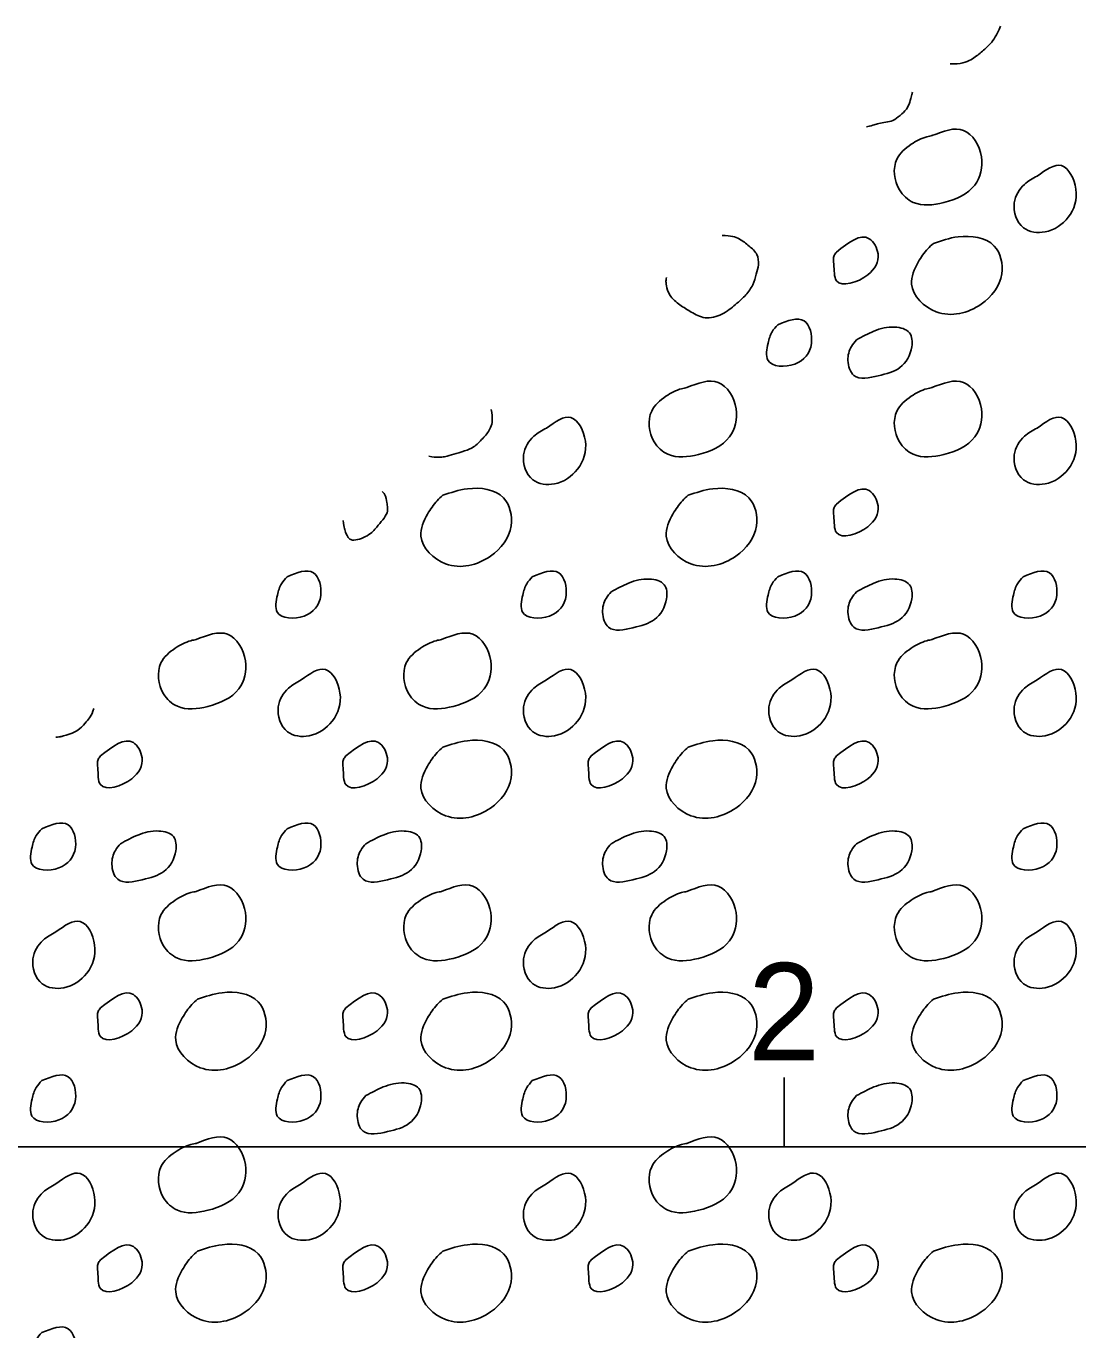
# Model space of a CAD drawing. Extents: x 0 to 1055, y 0 to 220.
# Drawn here: x 206.57 to 221.73, y 144.12 to 162.91 of the extents above; entities that cross this region are included whole.
import ezdxf

# ---------------------------------------------------------------- set-up
doc = ezdxf.new("R2010")
doc.units = 0
for name, color, linetype in [('DR_P_Culvert', 7, 'Continuous'), ('SC_Scratch1', 7, 'Continuous'), ('TX_P_5', 7, 'Continuous')]:
    doc.layers.add(name, color=color, linetype=linetype)

msp = doc.modelspace()

# ---------------------------------------------------------------- linework, layer by layer
at = {"layer": 'DR_P_Culvert'}
msp.add_line((17.5, 146.757), (317.5, 146.757), dxfattribs=at)
at = {"layer": 'SC_Scratch1'}
for points in [[(220.616, 162.908), (220.565, 162.773), (220.472, 162.645), (220.34, 162.532), (220.21, 162.421), (220.045, 162.356), (219.892, 162.363)], [(219.348, 161.954), (219.346, 161.941), (219.343, 161.929), (219.34, 161.917), (219.31, 161.812), (219.271, 161.705), (219.169, 161.62), (219.069, 161.537), (218.963, 161.525), (218.855, 161.5), (218.802, 161.487), (218.745, 161.466), (218.688, 161.457)], [(216.605, 159.89), (216.734, 159.892), (216.863, 159.847), (216.992, 159.739), (217.126, 159.627), (217.135, 159.461), (217.1, 159.337), (217.055, 159.18), (216.956, 159.031), (216.804, 158.902), (216.614, 158.739), (216.35, 158.676), (216.155, 158.791), (215.998, 158.884), (215.832, 159.024), (215.801, 159.189), (215.795, 159.22), (215.796, 159.253), (215.802, 159.285)], [(213.275, 157.384), (213.305, 157.257), (213.281, 157.105), (213.175, 156.988), (213.042, 156.84), (212.894, 156.784), (212.73, 156.735), (212.618, 156.702), (212.495, 156.686), (212.38, 156.71)], [(211.706, 156.203), (211.751, 156.164), (211.776, 156.051), (211.781, 155.995), (211.791, 155.896), (211.714, 155.792), (211.632, 155.693), (211.52, 155.559), (211.24, 155.461), (211.182, 155.609), (211.16, 155.665), (211.151, 155.723), (211.146, 155.782)], [(207.552, 153.077), (207.532, 153.014), (207.499, 152.951), (207.45, 152.893), (207.351, 152.774), (207.237, 152.717), (207.117, 152.681), (207.081, 152.67), (207.041, 152.662), (207.001, 152.662)]]:
    msp.add_open_spline(points, degree=3, dxfattribs=at)
for points in [[(219.63, 161.329), (220.085, 161.405), (220.344, 161.025), (220.247, 160.618), (219.801, 160.366), (219.361, 160.368), (219.162, 160.547), (219.125, 160.992), (219.33, 161.205), (219.556, 161.313), (219.639, 161.331)], [(221.146, 160.747), (221.498, 160.897), (221.705, 160.559), (221.594, 160.154), (221.26, 159.942), (220.95, 160.001), (220.816, 160.36), (220.962, 160.627), (221.146, 160.747)], [(218.252, 159.652), (218.727, 159.844), (218.853, 159.626), (218.704, 159.323), (218.254, 159.239), (218.215, 159.479), (218.219, 159.6), (218.252, 159.652)], [(219.651, 159.777), (220.007, 159.871), (220.528, 159.739), (220.635, 159.337), (220.34, 158.902), (219.691, 158.791), (219.337, 159.189), (219.432, 159.507), (219.57, 159.7), (219.651, 159.777)], [(217.406, 158.604), (217.788, 158.66), (217.892, 158.332), (217.652, 158.038), (217.265, 158.094), (217.268, 158.34), (217.326, 158.504), (217.406, 158.604)], [(218.544, 158.388), (218.794, 158.513), (219.095, 158.57), (219.305, 158.489), (219.34, 158.286), (219.169, 157.989), (218.855, 157.869), (218.504, 157.875), (218.418, 158.091), (218.47, 158.291), (218.544, 158.388)], [(216.095, 157.699), (216.549, 157.774), (216.808, 157.394), (216.711, 156.988), (216.265, 156.735), (215.825, 156.738), (215.626, 156.916), (215.59, 157.361), (215.795, 157.574), (216.02, 157.683), (216.103, 157.7)], [(219.63, 157.699), (220.085, 157.774), (220.344, 157.394), (220.247, 156.988), (219.801, 156.735), (219.361, 156.738), (219.162, 156.916), (219.125, 157.361), (219.33, 157.574), (219.556, 157.683), (219.639, 157.7)], [(214.075, 157.116), (214.426, 157.267), (214.634, 156.929), (214.522, 156.524), (214.189, 156.311), (213.878, 156.37), (213.745, 156.729), (213.89, 156.997), (214.075, 157.116)], [(221.146, 157.116), (221.498, 157.267), (221.705, 156.929), (221.594, 156.524), (221.26, 156.311), (220.95, 156.37), (220.816, 156.729), (220.962, 156.997), (221.146, 157.116)], [(212.58, 156.147), (212.935, 156.24), (213.456, 156.109), (213.564, 155.706), (213.268, 155.271), (212.62, 155.16), (212.265, 155.559), (212.36, 155.877), (212.499, 156.069), (212.58, 156.147)], [(216.115, 156.147), (216.471, 156.24), (216.992, 156.109), (217.1, 155.706), (216.804, 155.271), (216.155, 155.16), (215.801, 155.559), (215.896, 155.877), (216.035, 156.069), (216.115, 156.147)], [(218.252, 156.021), (218.727, 156.214), (218.853, 155.995), (218.704, 155.693), (218.254, 155.609), (218.215, 155.849), (218.219, 155.969), (218.252, 156.021)], [(210.335, 154.974), (210.716, 155.03), (210.82, 154.701), (210.58, 154.407), (210.194, 154.464), (210.196, 154.71), (210.255, 154.873), (210.335, 154.974)], [(213.87, 154.974), (214.252, 155.03), (214.356, 154.701), (214.116, 154.407), (213.73, 154.464), (213.732, 154.71), (213.79, 154.873), (213.87, 154.974)], [(217.406, 154.974), (217.788, 155.03), (217.892, 154.701), (217.652, 154.407), (217.265, 154.464), (217.268, 154.71), (217.326, 154.873), (217.406, 154.974)], [(220.942, 154.974), (221.324, 155.03), (221.428, 154.701), (221.188, 154.407), (220.801, 154.464), (220.804, 154.71), (220.862, 154.873), (220.942, 154.974)], [(215.008, 154.757), (215.258, 154.882), (215.559, 154.94), (215.77, 154.859), (215.804, 154.656), (215.633, 154.359), (215.32, 154.239), (214.968, 154.245), (214.882, 154.461), (214.934, 154.661), (215.008, 154.757)], [(218.544, 154.757), (218.794, 154.882), (219.095, 154.94), (219.305, 154.859), (219.34, 154.656), (219.169, 154.359), (218.855, 154.239), (218.504, 154.245), (218.418, 154.461), (218.47, 154.661), (218.544, 154.757)], [(209.023, 154.068), (209.477, 154.144), (209.736, 153.764), (209.64, 153.357), (209.194, 153.105), (208.754, 153.107), (208.555, 153.286), (208.518, 153.731), (208.723, 153.944), (208.949, 154.052), (209.031, 154.07)], [(212.559, 154.068), (213.013, 154.144), (213.272, 153.764), (213.175, 153.357), (212.73, 153.105), (212.29, 153.107), (212.09, 153.286), (212.054, 153.731), (212.259, 153.944), (212.485, 154.052), (212.567, 154.07)], [(219.63, 154.068), (220.085, 154.144), (220.344, 153.764), (220.247, 153.357), (219.801, 153.105), (219.361, 153.107), (219.162, 153.286), (219.125, 153.731), (219.33, 153.944), (219.556, 154.052), (219.639, 154.07)], [(210.539, 153.486), (210.89, 153.636), (211.098, 153.298), (210.986, 152.893), (210.653, 152.681), (210.342, 152.74), (210.209, 153.099), (210.355, 153.366), (210.539, 153.486)], [(214.075, 153.486), (214.426, 153.636), (214.634, 153.298), (214.522, 152.893), (214.189, 152.681), (213.878, 152.74), (213.745, 153.099), (213.89, 153.366), (214.075, 153.486)], [(217.61, 153.486), (217.962, 153.636), (218.17, 153.298), (218.058, 152.893), (217.725, 152.681), (217.414, 152.74), (217.28, 153.099), (217.426, 153.366), (217.61, 153.486)], [(221.146, 153.486), (221.498, 153.636), (221.705, 153.298), (221.594, 152.893), (221.26, 152.681), (220.95, 152.74), (220.816, 153.099), (220.962, 153.366), (221.146, 153.486)], [(207.645, 152.391), (208.12, 152.583), (208.245, 152.365), (208.096, 152.062), (207.646, 151.978), (207.607, 152.218), (207.611, 152.339), (207.645, 152.391)], [(211.18, 152.391), (211.655, 152.583), (211.781, 152.365), (211.632, 152.062), (211.182, 151.978), (211.143, 152.218), (211.147, 152.339), (211.18, 152.391)], [(212.58, 152.516), (212.935, 152.61), (213.456, 152.478), (213.564, 152.076), (213.268, 151.641), (212.62, 151.53), (212.265, 151.928), (212.36, 152.246), (212.499, 152.439), (212.58, 152.516)], [(214.716, 152.391), (215.191, 152.583), (215.317, 152.365), (215.168, 152.062), (214.718, 151.978), (214.679, 152.218), (214.683, 152.339), (214.716, 152.391)], [(216.115, 152.516), (216.471, 152.61), (216.992, 152.478), (217.1, 152.076), (216.804, 151.641), (216.155, 151.53), (215.801, 151.928), (215.896, 152.246), (216.035, 152.439), (216.115, 152.516)], [(218.252, 152.391), (218.727, 152.583), (218.853, 152.365), (218.704, 152.062), (218.254, 151.978), (218.215, 152.218), (218.219, 152.339), (218.252, 152.391)], [(206.799, 151.343), (207.18, 151.399), (207.285, 151.071), (207.045, 150.777), (206.658, 150.833), (206.66, 151.079), (206.719, 151.243), (206.799, 151.343)], [(210.335, 151.343), (210.716, 151.399), (210.82, 151.071), (210.58, 150.777), (210.194, 150.833), (210.196, 151.079), (210.255, 151.243), (210.335, 151.343)], [(220.942, 151.343), (221.324, 151.399), (221.428, 151.071), (221.188, 150.777), (220.801, 150.833), (220.804, 151.079), (220.862, 151.243), (220.942, 151.343)], [(207.936, 151.127), (208.186, 151.252), (208.487, 151.309), (208.698, 151.228), (208.732, 151.025), (208.561, 150.728), (208.248, 150.608), (207.896, 150.614), (207.81, 150.83), (207.862, 151.03), (207.936, 151.127)], [(211.472, 151.127), (211.722, 151.252), (212.023, 151.309), (212.234, 151.228), (212.268, 151.025), (212.097, 150.728), (211.784, 150.608), (211.432, 150.614), (211.346, 150.83), (211.398, 151.03), (211.472, 151.127)], [(215.008, 151.127), (215.258, 151.252), (215.559, 151.309), (215.77, 151.228), (215.804, 151.025), (215.633, 150.728), (215.32, 150.608), (214.968, 150.614), (214.882, 150.83), (214.934, 151.03), (215.008, 151.127)], [(218.544, 151.127), (218.794, 151.252), (219.095, 151.309), (219.305, 151.228), (219.34, 151.025), (219.169, 150.728), (218.855, 150.608), (218.504, 150.614), (218.418, 150.83), (218.47, 151.03), (218.544, 151.127)], [(209.023, 150.438), (209.477, 150.513), (209.736, 150.133), (209.64, 149.727), (209.194, 149.474), (208.754, 149.477), (208.555, 149.655), (208.518, 150.1), (208.723, 150.313), (208.949, 150.422), (209.031, 150.439)], [(212.559, 150.438), (213.013, 150.513), (213.272, 150.133), (213.175, 149.727), (212.73, 149.474), (212.29, 149.477), (212.09, 149.655), (212.054, 150.1), (212.259, 150.313), (212.485, 150.422), (212.567, 150.439)], [(216.095, 150.438), (216.549, 150.513), (216.808, 150.133), (216.711, 149.727), (216.265, 149.474), (215.825, 149.477), (215.626, 149.655), (215.59, 150.1), (215.795, 150.313), (216.02, 150.422), (216.103, 150.439)], [(219.63, 150.438), (220.085, 150.513), (220.344, 150.133), (220.247, 149.727), (219.801, 149.474), (219.361, 149.477), (219.162, 149.655), (219.125, 150.1), (219.33, 150.313), (219.556, 150.422), (219.639, 150.439)], [(207.003, 149.855), (207.355, 150.006), (207.562, 149.668), (207.45, 149.263), (207.117, 149.05), (206.806, 149.109), (206.673, 149.468), (206.819, 149.736), (207.003, 149.855)], [(214.075, 149.855), (214.426, 150.006), (214.634, 149.668), (214.522, 149.263), (214.189, 149.05), (213.878, 149.109), (213.745, 149.468), (213.89, 149.736), (214.075, 149.855)], [(221.146, 149.855), (221.498, 150.006), (221.705, 149.668), (221.594, 149.263), (221.26, 149.05), (220.95, 149.109), (220.816, 149.468), (220.962, 149.736), (221.146, 149.855)], [(207.645, 148.76), (208.12, 148.953), (208.245, 148.734), (208.096, 148.432), (207.646, 148.348), (207.607, 148.588), (207.611, 148.708), (207.645, 148.76)], [(209.044, 148.886), (209.4, 148.979), (209.92, 148.848), (210.028, 148.445), (209.732, 148.01), (209.084, 147.899), (208.73, 148.298), (208.825, 148.616), (208.963, 148.808), (209.044, 148.886)], [(211.18, 148.76), (211.655, 148.953), (211.781, 148.734), (211.632, 148.432), (211.182, 148.348), (211.143, 148.588), (211.147, 148.708), (211.18, 148.76)], [(212.58, 148.886), (212.935, 148.979), (213.456, 148.848), (213.564, 148.445), (213.268, 148.01), (212.62, 147.899), (212.265, 148.298), (212.36, 148.616), (212.499, 148.808), (212.58, 148.886)], [(214.716, 148.76), (215.191, 148.953), (215.317, 148.734), (215.168, 148.432), (214.718, 148.348), (214.679, 148.588), (214.683, 148.708), (214.716, 148.76)], [(216.115, 148.886), (216.471, 148.979), (216.992, 148.848), (217.1, 148.445), (216.804, 148.01), (216.155, 147.899), (215.801, 148.298), (215.896, 148.616), (216.035, 148.808), (216.115, 148.886)], [(218.252, 148.76), (218.727, 148.953), (218.853, 148.734), (218.704, 148.432), (218.254, 148.348), (218.215, 148.588), (218.219, 148.708), (218.252, 148.76)], [(219.651, 148.886), (220.007, 148.979), (220.528, 148.848), (220.635, 148.445), (220.34, 148.01), (219.691, 147.899), (219.337, 148.298), (219.432, 148.616), (219.57, 148.808), (219.651, 148.886)], [(206.799, 147.713), (207.18, 147.769), (207.285, 147.44), (207.045, 147.146), (206.658, 147.203), (206.66, 147.449), (206.719, 147.612), (206.799, 147.713)], [(210.335, 147.713), (210.716, 147.769), (210.82, 147.44), (210.58, 147.146), (210.194, 147.203), (210.196, 147.449), (210.255, 147.612), (210.335, 147.713)], [(211.472, 147.496), (211.722, 147.621), (212.023, 147.679), (212.234, 147.598), (212.268, 147.395), (212.097, 147.098), (211.784, 146.978), (211.432, 146.984), (211.346, 147.2), (211.398, 147.4), (211.472, 147.496)], [(213.87, 147.713), (214.252, 147.769), (214.356, 147.44), (214.116, 147.146), (213.73, 147.203), (213.732, 147.449), (213.79, 147.612), (213.87, 147.713)], [(218.544, 147.496), (218.794, 147.621), (219.095, 147.679), (219.305, 147.598), (219.34, 147.395), (219.169, 147.098), (218.855, 146.978), (218.504, 146.984), (218.418, 147.2), (218.47, 147.4), (218.544, 147.496)], [(220.942, 147.713), (221.324, 147.769), (221.428, 147.44), (221.188, 147.146), (220.801, 147.203), (220.804, 147.449), (220.862, 147.612), (220.942, 147.713)], [(209.023, 146.807), (209.477, 146.883), (209.736, 146.503), (209.64, 146.096), (209.194, 145.844), (208.754, 145.846), (208.555, 146.025), (208.518, 146.47), (208.723, 146.683), (208.949, 146.791), (209.031, 146.809)], [(216.095, 146.807), (216.549, 146.883), (216.808, 146.503), (216.711, 146.096), (216.265, 145.844), (215.825, 145.846), (215.626, 146.025), (215.59, 146.47), (215.795, 146.683), (216.02, 146.791), (216.103, 146.809)], [(207.003, 146.225), (207.355, 146.375), (207.562, 146.037), (207.45, 145.632), (207.117, 145.42), (206.806, 145.479), (206.673, 145.838), (206.819, 146.105), (207.003, 146.225)], [(210.539, 146.225), (210.89, 146.375), (211.098, 146.037), (210.986, 145.632), (210.653, 145.42), (210.342, 145.479), (210.209, 145.838), (210.355, 146.105), (210.539, 146.225)], [(214.075, 146.225), (214.426, 146.375), (214.634, 146.037), (214.522, 145.632), (214.189, 145.42), (213.878, 145.479), (213.745, 145.838), (213.89, 146.105), (214.075, 146.225)], [(217.61, 146.225), (217.962, 146.375), (218.17, 146.037), (218.058, 145.632), (217.725, 145.42), (217.414, 145.479), (217.28, 145.838), (217.426, 146.105), (217.61, 146.225)], [(221.146, 146.225), (221.498, 146.375), (221.705, 146.037), (221.594, 145.632), (221.26, 145.42), (220.95, 145.479), (220.816, 145.838), (220.962, 146.105), (221.146, 146.225)], [(207.645, 145.13), (208.12, 145.322), (208.245, 145.104), (208.096, 144.801), (207.646, 144.717), (207.607, 144.957), (207.611, 145.078), (207.645, 145.13)], [(209.044, 145.255), (209.4, 145.349), (209.92, 145.217), (210.028, 144.815), (209.732, 144.38), (209.084, 144.269), (208.73, 144.667), (208.825, 144.985), (208.963, 145.178), (209.044, 145.255)], [(211.18, 145.13), (211.655, 145.322), (211.781, 145.104), (211.632, 144.801), (211.182, 144.717), (211.143, 144.957), (211.147, 145.078), (211.18, 145.13)], [(212.58, 145.255), (212.935, 145.349), (213.456, 145.217), (213.564, 144.815), (213.268, 144.38), (212.62, 144.269), (212.265, 144.667), (212.36, 144.985), (212.499, 145.178), (212.58, 145.255)], [(214.716, 145.13), (215.191, 145.322), (215.317, 145.104), (215.168, 144.801), (214.718, 144.717), (214.679, 144.957), (214.683, 145.078), (214.716, 145.13)], [(216.115, 145.255), (216.471, 145.349), (216.992, 145.217), (217.1, 144.815), (216.804, 144.38), (216.155, 144.269), (215.801, 144.667), (215.896, 144.985), (216.035, 145.178), (216.115, 145.255)], [(218.252, 145.13), (218.727, 145.322), (218.853, 145.104), (218.704, 144.801), (218.254, 144.717), (218.215, 144.957), (218.219, 145.078), (218.252, 145.13)], [(219.651, 145.255), (220.007, 145.349), (220.528, 145.217), (220.635, 144.815), (220.34, 144.38), (219.691, 144.269), (219.337, 144.667), (219.432, 144.985), (219.57, 145.178), (219.651, 145.255)], [(206.799, 144.082), (207.18, 144.138), (207.285, 143.81), (207.045, 143.516), (206.658, 143.572), (206.66, 143.818), (206.719, 143.982), (206.799, 144.082)]]:
    msp.add_spline(points, degree=3, dxfattribs=at)
at = {"layer": 'TX_P_5'}
msp.add_line((217.5, 146.757), (217.5, 147.757), dxfattribs=at)

# ---------------------------------------------------------------- texts
msp.add_text('2', height=1.4, dxfattribs=at).set_placement((216.977, 148.007))

doc.saveas('drawing.dxf')
